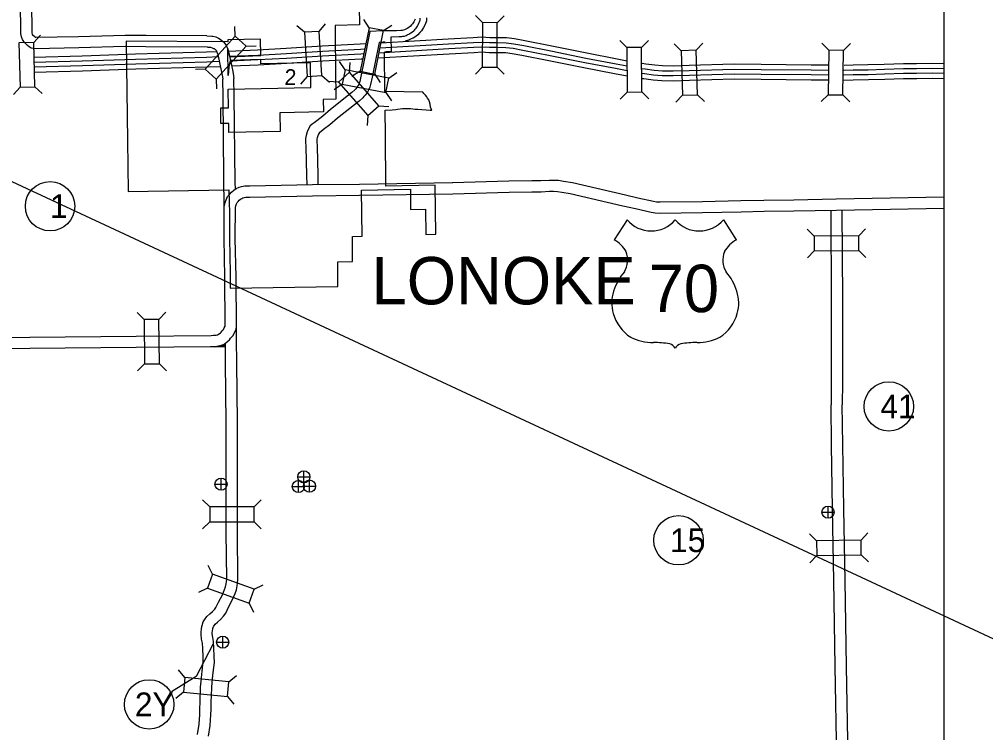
# Model space of a CAD drawing. Extents: x 1127717 to 1741049, y 2026793 to 2244711.
# Drawn here: x 1257093 to 1270013, y 2131052 to 2140586 of the extents above; entities that cross this region are included whole.
import ezdxf

# ---------------------------------------------------------------- set-up
doc = ezdxf.new("R2010")
doc.units = 0
for name, color, linetype in [('1', 7, 'Continuous'), ('10', 7, 'Continuous'), ('15', 7, 'Continuous'), ('19', 7, 'Continuous'), ('20', 7, 'Continuous'), ('22', 7, 'Continuous'), ('26', 7, 'Continuous'), ('27', 7, 'Continuous'), ('6', 7, 'Continuous'), ('R_Draft', 7, 'Continuous')]:
    doc.layers.add(name, color=color, linetype=linetype)

msp = doc.modelspace()

# ---------------------------------------------------------------- linework, layer by layer
at = {"layer": '1'}
msp.add_lwpolyline([(1238438, 2155644), (1269452, 2155644), (1269452, 2123596), (1238438, 2123596)], close=True, dxfattribs=at)
at = {"layer": '10'}
for points in [[(1259610, 2140215), (1258786, 2140220), (1258509, 2140222), (1257888, 2140203), (1257299, 2140191), (1257252, 2140200), (1257224, 2140219), (1257202, 2140236), (1257180, 2140257), (1257160, 2140275), (1257134, 2140318), (1257122, 2140352), (1257115, 2140396), (1257115, 2140445), (1257096, 2141771)], [(1259602, 2140365), (1258787, 2140370), (1258507, 2140372), (1257884, 2140353), (1257313, 2140341), (1257311, 2140341), (1257301, 2140350), (1257282, 2140367), (1257277, 2140372), (1257270, 2140383), (1257268, 2140389), (1257265, 2140407), (1257265, 2140447), (1257246, 2141776)], [(1262385, 2140589), (1262381, 2140578), (1262366, 2140553), (1262350, 2140524), (1262337, 2140511), (1262317, 2140490), (1262303, 2140479), (1262286, 2140467), (1262271, 2140460), (1262241, 2140446), (1262212, 2140437), (1262193, 2140435), (1262136, 2140431), (1261955, 2140430), (1261779, 2140425), (1261698, 2140018), (1261662, 2139844), (1261644, 2139753), (1261637, 2139731), (1261630, 2139714), (1261622, 2139700), (1261611, 2139683), (1261602, 2139670), (1261591, 2139658), (1261577, 2139642), (1261540, 2139610), (1261254, 2139381), (1261149, 2139293), (1261069, 2139231), (1261034, 2139203), (1261008, 2139185), (1260983, 2139162), (1260958, 2139122), (1260941, 2139082), (1260926, 2139035), (1260920, 2138994), (1260921, 2138954), (1260923, 2138880), (1260932, 2138498), (1260936, 2138376)], [(1262535, 2140605), (1262535, 2140566), (1262519, 2140516), (1262496, 2140477), (1262470, 2140433), (1262446, 2140408), (1262419, 2140379), (1262392, 2140358), (1262360, 2140336), (1262333, 2140324), (1262295, 2140306), (1262250, 2140292)], [(1259602, 2140365), (1259665, 2140362), (1259681, 2140359), (1259718, 2140350), (1259756, 2140334), (1259779, 2140321), (1259806, 2140300), (1259821, 2140286), (1259841, 2140263), (1259860, 2140234), (1259876, 2140197), (1259880, 2140183), (1259890, 2140155), (1259945, 2139909), (1259953, 2139863), (1259963, 2139795)], [(1259610, 2140215), (1259636, 2140215), (1259649, 2140212), (1259671, 2140207), (1259691, 2140198), (1259696, 2140196), (1259708, 2140186), (1259714, 2140181), (1259721, 2140173), (1259727, 2140163), (1259735, 2140146), (1259737, 2140137), (1259745, 2140114), (1259798, 2139879), (1259804, 2139843), (1259813, 2139786)], [(1261986, 2140280), (1261957, 2140280), (1261903, 2140278), (1261845, 2139989), (1261809, 2139815), (1261790, 2139717), (1261778, 2139680), (1261765, 2139647), (1261751, 2139623), (1261737, 2139601), (1261717, 2139572), (1261700, 2139556), (1261684, 2139537), (1261636, 2139494), (1261349, 2139265), (1261244, 2139176), (1261161, 2139113), (1261123, 2139082), (1261102, 2139068), (1261101, 2139066), (1261092, 2139052), (1261082, 2139029), (1261073, 2139002), (1261071, 2138985), (1261071, 2138957), (1261073, 2138884), (1261082, 2138502), (1261086, 2138379)], [(1259829, 2138476), (1259817, 2139561), (1259813, 2139786)], [(1259980, 2138403), (1259967, 2139563), (1259963, 2139795)], [(1259833, 2138084), (1259829, 2138473)], [(1259981, 2138321), (1259980, 2138403)], [(1267941, 2138033), (1267949, 2136844), (1267947, 2135738), (1267946, 2135433)], [(1268091, 2138036), (1268099, 2136845), (1268097, 2135738), (1268096, 2135433)], [(1260008, 2135201), (1259999, 2135995), (1259998, 2136296), (1259997, 2136478)], [(1259848, 2136207), (1259650, 2136208)], [(1259858, 2135199), (1259849, 2135994), (1259848, 2136259)], [(1268077, 2127140), (1268060, 2128459), (1268043, 2129518), (1268024, 2130697), (1268001, 2131934), (1267983, 2133084), (1267967, 2134041), (1267952, 2134899), (1267946, 2135432)], [(1268227, 2127142), (1268210, 2128461), (1268193, 2129520), (1268174, 2130699), (1268151, 2131936), (1268133, 2133086), (1268117, 2134043), (1268102, 2134901), (1268096, 2135433)], [(1259509, 2131461), (1259516, 2131660), (1259523, 2131741), (1259537, 2131874), (1259551, 2131997), (1259549, 2132067), (1259545, 2132175), (1259540, 2132250), (1259530, 2132302), (1259523, 2132363), (1259523, 2132395), (1259527, 2132438), (1259534, 2132472), (1259537, 2132485), (1259552, 2132531), (1259568, 2132558), (1259602, 2132604), (1259642, 2132639), (1259677, 2132671), (1259706, 2132702), (1259722, 2132726), (1259757, 2132795), (1259808, 2132896), (1259838, 2132966), (1259850, 2133000), (1259858, 2133041), (1259862, 2133067), (1259865, 2133105), (1259860, 2133733), (1259860, 2134971), (1259858, 2135199)], [(1259659, 2131456), (1259665, 2131650), (1259673, 2131726), (1259686, 2131858), (1259701, 2131990), (1259699, 2132072), (1259695, 2132183), (1259689, 2132270), (1259678, 2132325), (1259673, 2132372), (1259673, 2132388), (1259675, 2132415), (1259680, 2132438), (1259682, 2132444), (1259690, 2132470), (1259693, 2132476), (1259713, 2132502), (1259741, 2132527), (1259783, 2132565), (1259822, 2132608), (1259852, 2132649), (1259891, 2132728), (1259944, 2132833), (1259977, 2132911), (1259995, 2132960), (1260006, 2133014), (1260012, 2133051), (1260015, 2133101), (1260010, 2133733), (1260010, 2134972), (1260008, 2135201)], [(1259475, 2131027), (1259496, 2131164), (1259505, 2131296), (1259506, 2131370), (1259509, 2131460)], [(1259623, 2131004), (1259645, 2131148), (1259655, 2131289), (1259656, 2131367), (1259659, 2131456)]]:
    msp.add_lwpolyline(points, dxfattribs=at)
at = {"layer": '15'}
for points in [[(1259833, 2138089), (1259846, 2138136), (1259858, 2138174), (1259878, 2138216), (1259901, 2138245), (1259928, 2138277), (1259961, 2138303), (1259993, 2138325), (1260030, 2138341), (1260064, 2138351), (1260107, 2138360), (1260173, 2138359), (1261012, 2138378), (1261642, 2138385), (1262887, 2138403)], [(1262885, 2138403), (1263637, 2138428), (1263944, 2138432), (1264066, 2138432), (1264178, 2138437), (1264239, 2138438), (1264300, 2138435), (1264370, 2138425), (1264489, 2138405), (1265197, 2138241), (1265363, 2138202), (1265571, 2138155), (1265610, 2138148), (1265662, 2138145), (1266226, 2138152), (1266740, 2138163), (1267048, 2138170), (1267446, 2138175), (1268014, 2138185), (1268737, 2138198), (1269452, 2138212)], [(1259983, 2138069), (1259989, 2138093), (1259998, 2138119), (1260007, 2138138), (1260017, 2138151), (1260032, 2138168), (1260048, 2138181), (1260066, 2138193), (1260082, 2138200), (1260101, 2138206), (1260121, 2138210), (1260174, 2138209), (1261014, 2138228), (1261643, 2138235), (1262889, 2138253)], [(1262890, 2138253), (1263641, 2138278), (1263944, 2138282), (1264069, 2138282), (1264182, 2138287), (1264236, 2138288), (1264286, 2138285), (1264347, 2138277), (1264459, 2138257), (1265163, 2138095), (1265330, 2138056), (1265542, 2138007), (1265594, 2137999), (1265658, 2137995), (1266228, 2138002), (1266743, 2138013), (1267050, 2138020), (1267448, 2138025), (1268017, 2138035), (1268740, 2138048), (1269452, 2138062)], [(1259847, 2136494), (1259840, 2137138), (1259830, 2137657), (1259833, 2138089)], [(1259997, 2136478), (1259990, 2137141), (1259980, 2137658), (1259983, 2138069)], [(1253555, 2136290), (1254583, 2136297), (1255917, 2136317), (1257232, 2136339), (1258655, 2136352), (1259656, 2136361), (1259688, 2136363), (1259709, 2136364), (1259723, 2136366), (1259742, 2136370), (1259755, 2136376), (1259766, 2136383), (1259781, 2136395), (1259791, 2136405), (1259805, 2136422), (1259823, 2136442), (1259833, 2136461), (1259843, 2136485), (1259847, 2136495), (1259847, 2136494)], [(1253556, 2136140), (1254585, 2136147), (1255919, 2136167), (1257234, 2136189), (1258656, 2136202), (1259662, 2136211), (1259697, 2136213), (1259725, 2136214), (1259751, 2136219), (1259786, 2136226), (1259825, 2136242), (1259854, 2136261), (1259882, 2136284), (1259901, 2136304), (1259918, 2136323), (1259947, 2136355), (1259969, 2136397), (1259981, 2136426), (1259990, 2136446), (1259997, 2136478)]]:
    msp.add_lwpolyline(points, dxfattribs=at)
at = {"layer": '19'}
for points in [[(1261928, 2140273), (1262827, 2140326)], [(1262828, 2140326), (1263160, 2140344), (1263277, 2140351), (1263382, 2140344), (1263482, 2140344), (1263608, 2140342), (1263714, 2140328), (1263850, 2140304), (1264214, 2140230), (1264680, 2140136), (1265087, 2140060), (1265220, 2140033)], [(1259888, 2140162), (1260277, 2140178), (1260659, 2140200), (1261141, 2140231), (1261652, 2140257), (1261721, 2140261)], [(1259904, 2140093), (1260280, 2140109), (1260663, 2140131), (1261145, 2140162), (1261656, 2140188), (1261703, 2140191)], [(1261899, 2140140), (1262835, 2140195)], [(1261916, 2140204), (1262831, 2140257)], [(1262831, 2140257), (1263165, 2140275), (1263277, 2140282), (1263380, 2140276), (1263482, 2140275), (1263603, 2140273), (1263704, 2140260), (1263837, 2140236), (1264200, 2140163), (1264667, 2140068), (1265074, 2139992), (1265219, 2139963)], [(1262835, 2140195), (1263168, 2140213), (1263277, 2140220), (1263378, 2140213), (1263481, 2140213), (1263598, 2140211), (1263694, 2140199), (1263825, 2140175), (1264188, 2140101), (1264655, 2140007), (1265062, 2139931), (1265218, 2139900)], [(1257288, 2140081), (1257933, 2140098), (1258645, 2140123), (1259594, 2140150), (1259732, 2140155)], [(1257288, 2140012), (1257935, 2140030), (1258647, 2140054), (1259596, 2140081), (1259751, 2140087)], [(1259917, 2140032), (1260283, 2140047), (1260667, 2140069), (1261148, 2140100), (1261659, 2140126), (1261692, 2140128)], [(1259933, 2139963), (1260287, 2139978), (1260671, 2140000), (1261152, 2140031), (1261663, 2140057), (1261678, 2140058)], [(1261886, 2140070), (1262839, 2140126)], [(1262838, 2140126), (1263172, 2140144), (1263277, 2140151), (1263375, 2140144), (1263480, 2140144), (1263593, 2140142), (1263684, 2140131), (1263812, 2140108), (1264174, 2140034), (1264642, 2139940), (1265049, 2139864), (1265221, 2139829), (1265221, 2139829)], [(1257291, 2139950), (1257937, 2139967), (1258649, 2139991), (1259598, 2140018), (1259765, 2140025)], [(1257292, 2139881), (1257939, 2139898), (1258651, 2139923), (1259601, 2139950), (1259780, 2139957)], [(1265417, 2139929), (1265460, 2139924), (1265580, 2139908), (1265690, 2139899), (1265835, 2139897), (1266049, 2139904), (1266649, 2139921), (1267011, 2139917), (1267679, 2139910), (1267912, 2139907)], [(1265419, 2139998), (1265469, 2139992), (1265588, 2139976), (1265694, 2139967), (1265835, 2139965), (1266047, 2139972), (1266648, 2139990), (1267012, 2139986), (1267680, 2139978), (1267916, 2139976)], [(1268118, 2139907), (1268241, 2139910), (1268441, 2139912), (1268659, 2139919), (1268913, 2139928), (1269090, 2139927), (1269300, 2139933), (1269452, 2139928)], [(1268120, 2139975), (1268239, 2139979), (1268439, 2139981), (1268656, 2139988), (1268912, 2139997), (1269089, 2139996), (1269300, 2140001), (1269452, 2139996)], [(1265419, 2139866), (1265452, 2139862), (1265573, 2139846), (1265687, 2139836), (1265836, 2139834), (1266051, 2139841), (1266649, 2139859), (1267011, 2139855), (1267678, 2139847), (1267911, 2139844)], [(1265421, 2139796), (1265444, 2139793), (1265566, 2139777), (1265684, 2139768), (1265836, 2139765), (1266053, 2139772), (1266650, 2139790), (1267010, 2139786), (1267678, 2139778), (1267909, 2139776)], [(1268113, 2139775), (1268243, 2139779), (1268444, 2139781), (1268663, 2139788), (1268915, 2139797), (1269091, 2139796), (1269300, 2139801), (1269452, 2139796)], [(1268118, 2139844), (1268242, 2139847), (1268442, 2139850), (1268661, 2139857), (1268914, 2139866), (1269090, 2139865), (1269300, 2139870), (1269452, 2139865)]]:
    msp.add_lwpolyline(points, dxfattribs=at)
at = {"layer": '20'}
for p, q in [((1261770, 2140474), (1261698, 2140585)), ((1263285, 2140542), (1263192, 2140635)), ((1263483, 2140541), (1263577, 2140634)), ((1259980, 2140360), (1259974, 2140492)), ((1260904, 2140413), (1260804, 2140500)), ((1261101, 2140425), (1261188, 2140525)), ((1261964, 2140435), (1262074, 2140507)), ((1257286, 2140278), (1257377, 2140374)), ((1260126, 2140227), (1260258, 2140232)), ((1265214, 2140208), (1265120, 2140301)), ((1265412, 2140209), (1265505, 2140303)), ((1265943, 2140166), (1265847, 2140257)), ((1266141, 2140172), (1266231, 2140268)), ((1267914, 2140173), (1267822, 2140267)), ((1268112, 2140170), (1268207, 2140262)), ((1261449, 2139912), (1261375, 2140021)), ((1261509, 2139878), (1261518, 2140009)), ((1263283, 2139948), (1263190, 2139855)), ((1263481, 2139947), (1263574, 2139853)), ((1259579, 2139921), (1259447, 2139915)), ((1260941, 2139820), (1260854, 2139721)), ((1261139, 2139833), (1261238, 2139745)), ((1261650, 2139893), (1261540, 2139820)), ((1261844, 2139853), (1261917, 2139743)), ((1262032, 2139800), (1262141, 2139874)), ((1257104, 2139679), (1257013, 2139583)), ((1257302, 2139684), (1257397, 2139593)), ((1259725, 2139788), (1259731, 2139656)), ((1261360, 2139747), (1261228, 2139756)), ((1261411, 2139718), (1261302, 2139644)), ((1261995, 2139606), (1262069, 2139496)), ((1265218, 2139614), (1265125, 2139520)), ((1265416, 2139615), (1265510, 2139522)), ((1265960, 2139573), (1265870, 2139477)), ((1266158, 2139578), (1266254, 2139488)), ((1267907, 2139579), (1267813, 2139486)), ((1268105, 2139576), (1268197, 2139482)), ((1261900, 2139430), (1262032, 2139422)), ((1261751, 2139300), (1261742, 2139168)), ((1267721, 2137688), (1267627, 2137781)), ((1268315, 2137692), (1268408, 2137786)), ((1267722, 2137490), (1267630, 2137396)), ((1268316, 2137494), (1268410, 2137401)), ((1258761, 2136575), (1258667, 2136667)), ((1258959, 2136576), (1259052, 2136671)), ((1259697, 2136210), (1259845, 2136211)), ((1259733, 2136214), (1259846, 2136216)), ((1259845, 2136211), (1259733, 2136214)), ((1259757, 2136218), (1259845, 2136220)), ((1259846, 2136216), (1259757, 2136218)), ((1259773, 2136222), (1259845, 2136223)), ((1259845, 2136220), (1259773, 2136222)), ((1259790, 2136225), (1259845, 2136227)), ((1259845, 2136223), (1259790, 2136225)), ((1259800, 2136229), (1259844, 2136231)), ((1259845, 2136227), (1259800, 2136229)), ((1259809, 2136234), (1259844, 2136235)), ((1259844, 2136231), (1259809, 2136234)), ((1259819, 2136237), (1259846, 2136239)), ((1259844, 2136235), (1259819, 2136237)), ((1259827, 2136232), (1259821, 2136212)), ((1259826, 2136239), (1259846, 2136243)), ((1259846, 2136239), (1259826, 2136239)), ((1259828, 2136214), (1259827, 2136232)), ((1259832, 2136237), (1259828, 2136214)), ((1259833, 2136213), (1259832, 2136237)), ((1259836, 2136240), (1259833, 2136213)), ((1259834, 2136244), (1259846, 2136246)), ((1259846, 2136243), (1259834, 2136244)), ((1259840, 2136244), (1259835, 2136213)), ((1259835, 2136213), (1259836, 2136240)), ((1259838, 2136247), (1259846, 2136250)), ((1259846, 2136246), (1259838, 2136247)), ((1259844, 2136251), (1259840, 2136211)), ((1259840, 2136211), (1259840, 2136244)), ((1259842, 2136251), (1259846, 2136253)), ((1259846, 2136250), (1259842, 2136251)), ((1259843, 2136211), (1259844, 2136251)), ((1259845, 2136211), (1259843, 2136211)), ((1259846, 2136253), (1259845, 2136211)), ((1258767, 2135981), (1258674, 2135886)), ((1258965, 2135982), (1259059, 2135890)), ((1259638, 2134068), (1259544, 2134162)), ((1260232, 2134068), (1260325, 2134162)), ((1259638, 2133870), (1259544, 2133777)), ((1260232, 2133870), (1260325, 2133777)), ((1267752, 2133616), (1267657, 2133708)), ((1268346, 2133626), (1268438, 2133721)), ((1267755, 2133418), (1267664, 2133323)), ((1268349, 2133428), (1268444, 2133336)), ((1259674, 2133169), (1259618, 2133288)), ((1259608, 2132982), (1259489, 2132926)), ((1260234, 2132969), (1260353, 2133026)), ((1260167, 2132783), (1260224, 2132664)), ((1259305, 2131789), (1259221, 2131891)), ((1259896, 2131731), (1259998, 2131814)), ((1259286, 2131592), (1259184, 2131508)), ((1259877, 2131533), (1259961, 2131431))]:
    msp.add_line(p, q, dxfattribs=at)
for points in [[(1261844, 2139853), (1261964, 2140435), (1261770, 2140474), (1261650, 2139893)], [(1263285, 2140542), (1263283, 2139948), (1263481, 2139947), (1263483, 2140541)], [(1259725, 2139788), (1260126, 2140227), (1259980, 2140360), (1259579, 2139921)], [(1260904, 2140413), (1260941, 2139820), (1261139, 2139833), (1261101, 2140425)], [(1257302, 2139684), (1257286, 2140278), (1257088, 2140273), (1257104, 2139679)], [(1265214, 2140208), (1265218, 2139614), (1265416, 2139615), (1265412, 2140209)], [(1266158, 2139578), (1266141, 2140172), (1265943, 2140166), (1265960, 2139573)], [(1267914, 2140173), (1267907, 2139579), (1268105, 2139576), (1268112, 2140170)], [(1261360, 2139747), (1261751, 2139300), (1261900, 2139430), (1261509, 2139878)], [(1262032, 2139800), (1261449, 2139912), (1261411, 2139718), (1261995, 2139606)], [(1267722, 2137490), (1268316, 2137494), (1268315, 2137692), (1267721, 2137688)], [(1258761, 2136575), (1258767, 2135981), (1258965, 2135982), (1258959, 2136576)], [(1260232, 2134068), (1259638, 2134068), (1259638, 2133870), (1260232, 2133870)], [(1267755, 2133418), (1268349, 2133428), (1268346, 2133626), (1267752, 2133616)], [(1259608, 2132982), (1260167, 2132783), (1260234, 2132969), (1259674, 2133169)], [(1259896, 2131731), (1259305, 2131789), (1259286, 2131592), (1259877, 2131533)]]:
    msp.add_lwpolyline(points, close=True, dxfattribs=at)
at = {"layer": '22'}
for p, q in [((1265219, 2137907), (1265046, 2137639)), ((1266506, 2137907), (1266679, 2137639))]:
    msp.add_line(p, q, dxfattribs=at)
for centre, radius, start, end in [((1265541, 2138178), 421, 220.075, 319.6701), ((1266184, 2138178), 421, 220.3299, 319.925), ((1264820, 2137251), 450, 30.7809, 59.9883), ((1266905, 2137251), 450, 120.0117, 149.2191), ((1264919, 2137369), 308, 328.8105, 21.2108), ((1266806, 2137369), 308, 158.7892, 211.1895), ((1265725, 2136738), 719, 138.9565, 162.6913), ((1266000, 2136738), 719, 17.3087, 41.0435), ((1265487, 2136796), 475, 160.9576, 197.3819), ((1266237, 2136796), 475, 342.6181, 19.0424), ((1265565, 2136798), 550, 195.1074, 237.1312), ((1266160, 2136798), 550, 302.8688, 344.8926), ((1265575, 2136971), 706, 244.0771, 269.5779), ((1266150, 2136971), 706, 270.4221, 295.9229), ((1265591, 2134972), 1293, 81.1942, 90.9539), ((1265753, 2136131), 124, 28.0342, 72.9864), ((1265972, 2136131), 124, 107.0136, 151.9658), ((1266133, 2134972), 1293, 89.0461, 98.8058)]:
    msp.add_arc(centre, radius, start, end, dxfattribs=at)
at = {"layer": '26'}
for p, q in [((1260896, 2134389), (1260896, 2134551)), ((1259709, 2134373), (1259871, 2134373)), ((1259790, 2134292), (1259790, 2134454)), ((1260815, 2134470), (1260977, 2134470)), ((1260824, 2134261), (1260824, 2134424)), ((1260972, 2134265), (1260972, 2134428)), ((1260743, 2134343), (1260905, 2134343)), ((1260891, 2134347), (1261053, 2134347)), ((1267823, 2133999), (1267986, 2133999)), ((1267905, 2133918), (1267905, 2134080)), ((1259812, 2132181), (1259812, 2132343)), ((1259730, 2132262), (1259893, 2132262))]:
    msp.add_line(p, q, dxfattribs=at)
for centre in [(1260896, 2134470), (1259790, 2134373), (1260824, 2134343), (1260972, 2134347), (1267905, 2133999), (1259812, 2132262)]:
    msp.add_circle(centre, 81.2, dxfattribs=at)
at = {"layer": '27'}
msp.add_lwpolyline([(1259680, 2132230), (1259455, 2131802), (1259129, 2131598)], dxfattribs=at)
for centre in [(1257504, 2138088), (1268718, 2135412), (1265906, 2133623), (1258829, 2131430)]:
    msp.add_circle(centre, 330, dxfattribs=at)
at = {"layer": '6'}
for points in [[(1261631, 2141010), (1261642, 2140513), (1261315, 2140505), (1261317, 2140339), (1261324, 2139517), (1261157, 2139513), (1261159, 2139349), (1260576, 2139336), (1260579, 2139087)], [(1259904, 2137657), (1259910, 2137194), (1259912, 2137004), (1259912, 2136992), (1261352, 2137013), (1261350, 2137345), (1261548, 2137351), (1261546, 2137683), (1261676, 2137687), (1261667, 2138303), (1262321, 2138315), (1262325, 2138043), (1262523, 2138047), (1262527, 2137710), (1262660, 2137713), (1262653, 2138370), (1261995, 2138357), (1261987, 2139036), (1261984, 2139370), (1262076, 2139375), (1262127, 2139380), (1262151, 2139383), (1262185, 2139388), (1262218, 2139392), (1262247, 2139393), (1262286, 2139394), (1262324, 2139393), (1262386, 2139384), (1262419, 2139385), (1262584, 2139370), (1262597, 2139372), (1262604, 2139374), (1262607, 2139376), (1262598, 2139389), (1262590, 2139412), (1262584, 2139453), (1262577, 2139482), (1262566, 2139508), (1262552, 2139532), (1262539, 2139552), (1262523, 2139573), (1262502, 2139596), (1262487, 2139611), (1261981, 2139622), (1261975, 2140149), (1261984, 2140151), (1261991, 2140152), (1261997, 2140153), (1262003, 2140154), (1262009, 2140155), (1262016, 2140155), (1262023, 2140156), (1262032, 2140156), (1262067, 2140158), (1262063, 2140354), (1262173, 2140356), (1262197, 2140357), (1262207, 2140357), (1262219, 2140359), (1262227, 2140360), (1262241, 2140363), (1262264, 2140371), (1262278, 2140377), (1262287, 2140381), (1262301, 2140387), (1262316, 2140396), (1262329, 2140404), (1262351, 2140419), (1262366, 2140432), (1262377, 2140442), (1262386, 2140453), (1262397, 2140466), (1262407, 2140479), (1262418, 2140496), (1262426, 2140513), (1262436, 2140535), (1262442, 2140552), (1262448, 2140567), (1262450, 2140576), (1262452, 2140584), (1262454, 2140601)], [(1260579, 2139087), (1259894, 2139073), (1259892, 2139194), (1259786, 2139193), (1259785, 2139402), (1259890, 2139404), (1259887, 2139651), (1260989, 2139674), (1260985, 2140003), (1260322, 2139990), (1260321, 2140049), (1259912, 2140035), (1259907, 2140018), (1259901, 2139999), (1259897, 2139982), (1259894, 2139942), (1259885, 2139835), (1259881, 2140191), (1259889, 2140152), (1259893, 2140123), (1259898, 2140102), (1259904, 2140085), (1260320, 2140101), (1260317, 2140320), (1259880, 2140312), (1259880, 2140287), (1258521, 2140296), (1258541, 2138961), (1258546, 2138284), (1259895, 2138308), (1259899, 2138144), (1259898, 2138097), (1259901, 2138042), (1259901, 2137966), (1259903, 2137774), (1259904, 2137657)]]:
    msp.add_lwpolyline(points, dxfattribs=at)
at = {"layer": 'R_Draft'}
msp.add_line((1254334, 2139654), (1270984, 2131900), dxfattribs=at)

# ---------------------------------------------------------------- texts
at = {"layer": '20'}
msp.add_text('2', height=211, rotation=358, dxfattribs=at).set_placement((1260636, 2139711))
at = {"layer": '22'}
msp.add_text('70', height=633.6, dxfattribs=at).set_placement((1265506, 2136672))
at = {"layer": '27'}
for s, height, p in [('1', 317, (1257504, 2137930)), ('41', 316.8, (1268606, 2135253)), ('15', 316.8, (1265793, 2133465)), ('2Y', 316.8, (1258638, 2131272))]:
    msp.add_text(s, height=height, dxfattribs=at).set_placement(p)
at = {"layer": '6'}
msp.add_text('LONOKE', height=633.6, dxfattribs=at).set_placement((1261802, 2136776))

doc.saveas('drawing.dxf')
